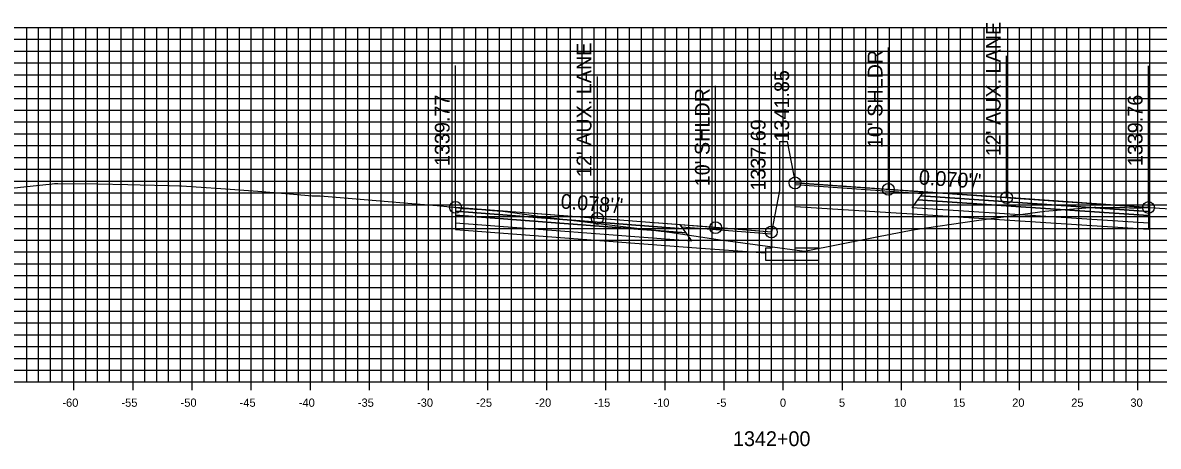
# Model space of a CAD drawing. Extents: x 674939 to 678919, y 750652 to 765176.
# Drawn here: x 678674.2 to 678770.3, y 752832.1 to 752868 of the extents above; entities that cross this region are included whole.
import ezdxf

# ---------------------------------------------------------------- set-up
doc = ezdxf.new("R2010")
doc.units = 0
for name, color, linetype in [('R_Alt Surface', 7, 'Continuous'), ('R_Axis', 7, 'Continuous'), ('R_Axis Annot', 7, 'Continuous'), ('R_Exist Surface', 7, 'Continuous'), ('R_Fin Surface', 7, 'Continuous'), ('R_Grid', 7, 'Continuous'), ('R_No Plot', 7, 'Continuous'), ('R_Proposed Road', 7, 'Continuous'), ('R_Xsect Elev', 7, 'Continuous'), ('R_Xsect Slope', 7, 'Continuous')]:
    doc.layers.add(name, color=color, linetype=linetype)

msp = doc.modelspace()

# ---------------------------------------------------------------- linework, layer by layer
at = {"layer": 'R_Alt Surface'}
for points in [[(678769.431, 752851.982), (678769.431, 752851.652), (678749.931, 752852.957), (678750.181, 752853.297)], [(678769.431, 752851.652), (678769.431, 752850.992), (678749.431, 752852.277), (678749.931, 752852.957)], [(678710.809, 752851.995), (678710.809, 752851.665), (678730.309, 752850.164), (678730.059, 752850.504)], [(678710.809, 752851.665), (678710.809, 752851.005), (678730.809, 752849.484), (678730.309, 752850.164)]]:
    msp.add_lwpolyline(points, close=True, dxfattribs=at)
for points in [[(678749.431, 752851.737), (678739.533, 752852.373)], [(678769.431, 752850.992), (678769.432, 752850.452), (678749.431, 752851.737)], [(678710.809, 752851.005), (678710.809, 752850.465), (678730.809, 752848.944)], [(678730.809, 752848.944), (678737.033, 752848.47)]]:
    msp.add_lwpolyline(points, dxfattribs=at)
at = {"layer": 'R_Axis'}
for p, q in [((678678.533, 752836.851), (678678.533, 752838.251)), ((678683.533, 752836.851), (678683.533, 752838.251)), ((678688.533, 752836.851), (678688.533, 752838.251)), ((678693.533, 752836.851), (678693.533, 752838.251)), ((678698.533, 752836.851), (678698.533, 752838.251)), ((678703.533, 752836.851), (678703.533, 752838.251)), ((678708.533, 752836.851), (678708.533, 752838.251)), ((678713.533, 752836.851), (678713.533, 752838.251)), ((678718.533, 752836.851), (678718.533, 752838.251)), ((678723.533, 752836.851), (678723.533, 752838.251)), ((678728.533, 752836.851), (678728.533, 752838.251)), ((678733.533, 752836.851), (678733.533, 752838.251)), ((678738.533, 752836.851), (678738.533, 752838.251)), ((678743.533, 752836.851), (678743.533, 752838.251)), ((678748.533, 752836.851), (678748.533, 752838.251)), ((678753.533, 752836.851), (678753.533, 752838.251)), ((678758.533, 752836.851), (678758.533, 752838.251)), ((678763.533, 752836.851), (678763.533, 752838.251)), ((678768.533, 752836.851), (678768.533, 752838.251)), ((678638.533, 752837.551), (678838.533, 752837.551))]:
    msp.add_line(p, q, dxfattribs=at)
at = {"layer": 'R_Exist Surface'}
msp.add_lwpolyline([(678663.579, 752852.93), (678676.691, 752854.319), (678676.895, 752854.332), (678677.179, 752854.348), (678680.535, 752854.304), (678683.09, 752854.267), (678684.135, 752854.24), (678686.592, 752854.17), (678687.457, 752854.146), (678687.473, 752854.146), (678687.619, 752854.141), (678690.946, 752853.909), (678694.081, 752853.693), (678697.101, 752853.441), (678698.689, 752853.308), (678699.04, 752853.311), (678699.372, 752853.308), (678704.105, 752852.909), (678707.45, 752852.634), (678709.246, 752852.474), (678710.368, 752852.379), (678710.66, 752852.348), (678710.809, 752852.325), (678710.877, 752852.318), (678711.238, 752852.264), (678711.409, 752852.238), (678712.012, 752852.208), (678712.409, 752852.178), (678712.726, 752852.168), (678713.936, 752852.068), (678714.094, 752852.048), (678714.173, 752852.049), (678714.488, 752852.018), (678714.548, 752852.026), (678714.626, 752852.038), (678717.032, 752851.702), (678718.18, 752851.522), (678720.375, 752851.272), (678728.909, 752850.218), (678733.016, 752849.612), (678740.344, 752848.607), (678746.443, 752849.82), (678749.494, 752850.425), (678754.877, 752851.22), (678760.672, 752851.991), (678764.831, 752852.343), (678764.965, 752852.354), (678765.228, 752852.327), (678765.248, 752852.327), (678765.251, 752852.327), (678767.419, 752852.315), (678767.428, 752852.315), (678767.821, 752852.288), (678767.848, 752852.287), (678768.834, 752852.285), (678768.843, 752852.286), (678769.237, 752852.323), (678769.239, 752852.323), (678769.431, 752852.312), (678774.151, 752852.03)], dxfattribs=at)
at = {"layer": 'R_Fin Surface'}
for points in [[(678769.431, 752852.312), (678757.431, 752853.149), (678747.431, 752853.846), (678739.533, 752854.397)], [(678737.533, 752850.241), (678732.809, 752850.61), (678722.809, 752851.39), (678710.809, 752852.325)]]:
    msp.add_lwpolyline(points, dxfattribs=at)
for points in [[(678750.313, 752853.477), (678739.533, 752854.237), (678739.533, 752854.397), (678750.431, 752853.637)], [(678769.431, 752852.312), (678769.431, 752851.982), (678750.181, 752853.297), (678750.431, 752853.637)], [(678710.809, 752852.325), (678710.809, 752851.995), (678730.059, 752850.504), (678729.809, 752850.844)], [(678729.927, 752850.683), (678737.533, 752850.081), (678737.533, 752850.241), (678729.809, 752850.844)]]:
    msp.add_lwpolyline(points, close=True, dxfattribs=at)
at = {"layer": 'R_Grid'}
for p, q in [((678638.533, 752867.551), (678838.533, 752867.551)), ((678674.533, 752837.551), (678674.533, 752867.551)), ((678675.533, 752837.551), (678675.533, 752867.551)), ((678676.533, 752837.551), (678676.533, 752867.551)), ((678677.533, 752837.551), (678677.533, 752867.551)), ((678678.533, 752837.551), (678678.533, 752867.551)), ((678679.533, 752837.551), (678679.533, 752867.551)), ((678680.533, 752837.551), (678680.533, 752867.551)), ((678681.533, 752837.551), (678681.533, 752867.551)), ((678682.533, 752837.551), (678682.533, 752867.551)), ((678683.533, 752837.551), (678683.533, 752867.551)), ((678684.533, 752837.551), (678684.533, 752867.551)), ((678685.533, 752837.551), (678685.533, 752867.551)), ((678686.533, 752837.551), (678686.533, 752867.551)), ((678687.533, 752837.551), (678687.533, 752867.551)), ((678688.533, 752837.551), (678688.533, 752867.551)), ((678689.533, 752837.551), (678689.533, 752867.551)), ((678690.533, 752837.551), (678690.533, 752867.551)), ((678691.533, 752837.551), (678691.533, 752867.551)), ((678692.533, 752837.551), (678692.533, 752867.551)), ((678693.533, 752837.551), (678693.533, 752867.551)), ((678694.533, 752837.551), (678694.533, 752867.551)), ((678695.533, 752837.551), (678695.533, 752867.551)), ((678696.533, 752837.551), (678696.533, 752867.551)), ((678697.533, 752837.551), (678697.533, 752867.551)), ((678698.533, 752837.551), (678698.533, 752867.551)), ((678699.533, 752837.551), (678699.533, 752867.551)), ((678700.533, 752837.551), (678700.533, 752867.551)), ((678701.533, 752837.551), (678701.533, 752867.551)), ((678702.533, 752837.551), (678702.533, 752867.551)), ((678703.533, 752837.551), (678703.533, 752867.551)), ((678704.533, 752837.551), (678704.533, 752867.551)), ((678705.533, 752837.551), (678705.533, 752867.551)), ((678706.533, 752837.551), (678706.533, 752867.551)), ((678707.533, 752837.551), (678707.533, 752867.551)), ((678708.533, 752837.551), (678708.533, 752867.551)), ((678709.533, 752837.551), (678709.533, 752867.551)), ((678710.533, 752837.551), (678710.533, 752867.551)), ((678711.533, 752837.551), (678711.533, 752867.551)), ((678712.533, 752837.551), (678712.533, 752867.551)), ((678713.533, 752837.551), (678713.533, 752867.551)), ((678714.533, 752837.551), (678714.533, 752867.551)), ((678715.533, 752837.551), (678715.533, 752867.551)), ((678716.533, 752837.551), (678716.533, 752867.551)), ((678717.533, 752837.551), (678717.533, 752867.551)), ((678718.533, 752837.551), (678718.533, 752867.551)), ((678719.533, 752837.551), (678719.533, 752867.551)), ((678720.533, 752837.551), (678720.533, 752867.551)), ((678721.533, 752837.551), (678721.533, 752867.551)), ((678722.533, 752837.551), (678722.533, 752867.551)), ((678723.533, 752837.551), (678723.533, 752867.551)), ((678724.533, 752837.551), (678724.533, 752867.551)), ((678725.533, 752837.551), (678725.533, 752867.551)), ((678726.533, 752837.551), (678726.533, 752867.551)), ((678727.533, 752837.551), (678727.533, 752867.551)), ((678728.533, 752837.551), (678728.533, 752867.551)), ((678729.533, 752837.551), (678729.533, 752867.551)), ((678730.533, 752837.551), (678730.533, 752867.551)), ((678731.533, 752837.551), (678731.533, 752867.551)), ((678732.533, 752837.551), (678732.533, 752867.551)), ((678733.533, 752837.551), (678733.533, 752867.551)), ((678734.533, 752837.551), (678734.533, 752867.551)), ((678735.533, 752837.551), (678735.533, 752867.551)), ((678736.533, 752837.551), (678736.533, 752867.551)), ((678737.533, 752837.551), (678737.533, 752867.551)), ((678738.533, 752837.551), (678738.533, 752867.551)), ((678739.533, 752837.551), (678739.533, 752867.551)), ((678740.533, 752837.551), (678740.533, 752867.551)), ((678741.533, 752837.551), (678741.533, 752867.551)), ((678742.533, 752837.551), (678742.533, 752867.551)), ((678743.533, 752837.551), (678743.533, 752867.551)), ((678744.533, 752837.551), (678744.533, 752867.551)), ((678745.533, 752837.551), (678745.533, 752867.551)), ((678746.533, 752837.551), (678746.533, 752867.551)), ((678747.533, 752837.551), (678747.533, 752867.551)), ((678748.533, 752837.551), (678748.533, 752867.551)), ((678749.533, 752837.551), (678749.533, 752867.551)), ((678750.533, 752837.551), (678750.533, 752867.551)), ((678751.533, 752837.551), (678751.533, 752867.551)), ((678752.533, 752837.551), (678752.533, 752867.551)), ((678753.533, 752837.551), (678753.533, 752867.551)), ((678754.533, 752837.551), (678754.533, 752867.551)), ((678755.533, 752837.551), (678755.533, 752867.551)), ((678756.533, 752837.551), (678756.533, 752867.551)), ((678757.533, 752837.551), (678757.533, 752867.551)), ((678758.533, 752837.551), (678758.533, 752867.551)), ((678759.533, 752837.551), (678759.533, 752867.551)), ((678760.533, 752837.551), (678760.533, 752867.551)), ((678761.533, 752837.551), (678761.533, 752867.551)), ((678762.533, 752837.551), (678762.533, 752867.551)), ((678763.533, 752837.551), (678763.533, 752867.551)), ((678764.533, 752837.551), (678764.533, 752867.551)), ((678765.533, 752837.551), (678765.533, 752867.551)), ((678766.533, 752837.551), (678766.533, 752867.551)), ((678767.533, 752837.551), (678767.533, 752867.551)), ((678768.533, 752837.551), (678768.533, 752867.551)), ((678769.533, 752837.551), (678769.533, 752867.551)), ((678638.533, 752866.551), (678838.533, 752866.551)), ((678638.533, 752865.551), (678838.533, 752865.551)), ((678638.533, 752864.551), (678838.533, 752864.551)), ((678638.533, 752863.551), (678838.533, 752863.551)), ((678638.533, 752862.551), (678838.533, 752862.551)), ((678638.533, 752861.551), (678838.533, 752861.551)), ((678638.533, 752860.551), (678838.533, 752860.551)), ((678638.533, 752859.551), (678838.533, 752859.551)), ((678638.533, 752858.551), (678838.533, 752858.551)), ((678638.533, 752857.551), (678838.533, 752857.551)), ((678638.533, 752856.551), (678838.533, 752856.551)), ((678638.533, 752855.551), (678838.533, 752855.551)), ((678638.533, 752854.551), (678838.533, 752854.551)), ((678638.533, 752853.551), (678838.533, 752853.551)), ((678638.533, 752852.551), (678838.533, 752852.551)), ((678638.533, 752851.551), (678838.533, 752851.551)), ((678638.533, 752850.551), (678838.533, 752850.551)), ((678638.533, 752849.551), (678838.533, 752849.551)), ((678638.533, 752848.551), (678838.533, 752848.551)), ((678638.533, 752847.551), (678838.533, 752847.551)), ((678638.533, 752846.551), (678838.533, 752846.551)), ((678638.533, 752845.551), (678838.533, 752845.551)), ((678638.533, 752844.551), (678838.533, 752844.551)), ((678638.533, 752843.551), (678838.533, 752843.551)), ((678638.533, 752842.551), (678838.533, 752842.551)), ((678638.533, 752841.551), (678838.533, 752841.551)), ((678638.533, 752840.551), (678838.533, 752840.551)), ((678638.533, 752839.551), (678838.533, 752839.551)), ((678638.533, 752838.551), (678838.533, 752838.551)), ((678638.533, 752837.551), (678838.533, 752837.551))]:
    msp.add_line(p, q, dxfattribs=at)
at = {"layer": 'R_No Plot'}
for centre in [(678739.533, 752854.397), (678747.431, 752853.846), (678757.431, 752853.149), (678710.809, 752852.325), (678769.431, 752852.312), (678722.809, 752851.39), (678732.809, 752850.61), (678737.533, 752850.241)]:
    msp.add_circle(centre, 0.5, dxfattribs=at)
at = {"layer": 'R_Proposed Road'}
for points in [[(678738.203, 752857.897), (678738.203, 752853.741)], [(678738.203, 752857.897), (678738.863, 752857.897)], [(678738.863, 752857.897), (678739.533, 752854.397)], [(678738.863, 752857.897), (678738.863, 752857.897)], [(678737.533, 752850.241), (678737.533, 752848.866), (678737.033, 752848.866), (678737.033, 752847.866), (678741.533, 752847.866), (678741.533, 752848.866), (678739.533, 752848.866), (678739.533, 752854.397)], [(678738.203, 752853.741), (678737.533, 752850.241)]]:
    msp.add_lwpolyline(points, dxfattribs=at)
at = {"layer": 'R_Xsect Elev'}
for p, q in [((678739.533, 752854.397), (678739.533, 752866.397)), ((678747.431, 752853.846), (678747.431, 752865.846)), ((678757.431, 752853.149), (678757.431, 752865.149)), ((678710.809, 752852.325), (678710.809, 752864.325)), ((678769.431, 752852.312), (678769.431, 752864.312)), ((678722.809, 752851.39), (678722.809, 752863.39)), ((678732.809, 752850.61), (678732.809, 752862.61)), ((678737.533, 752850.241), (678737.533, 752862.241))]:
    msp.add_line(p, q, dxfattribs=at)

# ---------------------------------------------------------------- texts
at = {"layer": 'R_Axis Annot'}
for s, height, p in [('-60', 0.7, (678677.552, 752835.451)), ('-55', 0.7, (678682.546, 752835.451)), ('-50', 0.7, (678687.552, 752835.451)), ('-45', 0.7, (678692.546, 752835.451)), ('-40', 0.7, (678697.552, 752835.451)), ('-35', 0.7, (678702.546, 752835.451)), ('-30', 0.7, (678707.552, 752835.451)), ('-25', 0.7, (678712.546, 752835.451)), ('-20', 0.7, (678717.552, 752835.451)), ('-15', 0.7, (678722.546, 752835.451)), ('-10', 0.7, (678727.552, 752835.451)), ('-5', 0.7, (678732.896, 752835.451)), ('0', 0.7, (678738.252, 752835.451)), ('5', 0.7, (678743.246, 752835.451)), ('10', 0.7, (678747.902, 752835.451)), ('15', 0.7, (678752.896, 752835.451)), ('20', 0.7, (678757.902, 752835.451)), ('25', 0.7, (678762.896, 752835.451)), ('30', 0.7, (678767.902, 752835.451)), ('1342+00', 1.25, (678734.281, 752832.126))]:
    msp.add_text(s, height=height, dxfattribs=at).set_placement(p)
at = {"layer": 'R_Xsect Elev'}
for s, p in [("12' AUX. LANE", (678756.931, 752856.649)), ("12' AUX. LANE", (678722.309, 752854.89)), ("10' SHLDR", (678746.931, 752857.346)), ('1341.85', (678739.033, 752857.897)), ('1339.77', (678710.309, 752855.825)), ("10' SHLDR", (678732.309, 752854.11)), ('1339.76', (678768.931, 752855.812)), ('1337.69', (678737.033, 752853.741))]:
    msp.add_text(s, height=1.25, rotation=90, dxfattribs=at).set_placement(p)
at = {"layer": 'R_Xsect Slope'}
for s, rotation, p in [("0.070'/'", 356.01173, (678749.972, 752854.27)), ("0.078'/'", 355.54038, (678719.669, 752852.236))]:
    msp.add_text(s, height=1.25, rotation=rotation, dxfattribs=at).set_placement(p)

doc.saveas('drawing.dxf')
